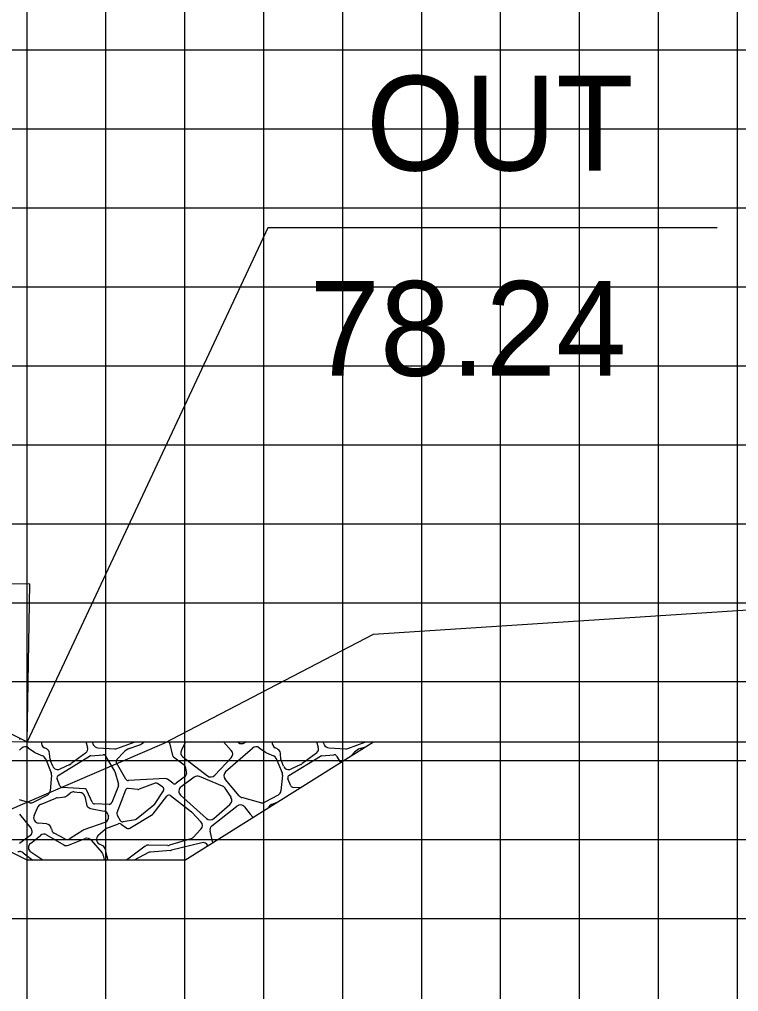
# Model space of a CAD drawing. Extents: x 857504 to 857847, y 364765 to 364985.
# Drawn here: x 857733.21 to 857742.32, y 364923.38 to 364935.69 of the extents above; entities that cross this region are included whole.
import ezdxf

# ---------------------------------------------------------------- set-up
doc = ezdxf.new("R2010")
doc.units = 0
for name, color, linetype in [('ANNOTATION', 7, 'Continuous'), ('D_Drainage_Culvert', 7, 'Continuous'), ('D_Roadway_Centerline', 7, 'Continuous'), ('D_Roadway_SlopeLines', 7, 'Continuous'), ('MAJOR', 7, 'Continuous'), ('MINOR', 7, 'Continuous'), ('S_Roadway_Centerline', 7, 'Continuous')]:
    doc.layers.add(name, color=color, linetype=linetype)

msp = doc.modelspace()

# ---------------------------------------------------------------- linework, layer by layer
at = {"layer": 'ANNOTATION'}
msp.add_lwpolyline([(857742.052, 364933.049), (857736.36, 364933.049), (857733.308, 364926.539)], dxfattribs=at)
at = {"layer": 'D_Drainage_Culvert'}
for p, q in [((857596.788, 364931.1), (857733.345, 364928.539)), ((857596.751, 364929.101), (857733.308, 364926.539)), ((857733.308, 364926.539), (857733.345, 364928.539))]:
    msp.add_line(p, q, dxfattribs=at)
at = {"layer": 'D_Roadway_Centerline'}
msp.add_lwpolyline([(857596.751, 364929.101), (857642.099, 364951.775), (857647.308, 364954.379), (857650.308, 364954.439), (857655.308, 364954.539), (857669.308, 364953.699), (857677.308, 364953.219), (857680.308, 364953.039), (857685.989, 364950.198), (857733.308, 364926.539)], dxfattribs=at)
at = {"layer": 'D_Roadway_SlopeLines'}
for p, q in [((857733.227, 364926.579), (857733.212, 364926.57)), ((857734.051, 364926.539), (857734.073, 364926.474)), ((857734.132, 364926.539), (857734.147, 364926.504)), ((857734.446, 364926.455), (857734.678, 364926.539)), ((857734.603, 364926.455), (857734.723, 364926.496)), ((857734.769, 364926.521), (857734.794, 364926.539)), ((857735.113, 364926.525), (857735.151, 364926.368)), ((857735.307, 364926.522), (857735.263, 364926.433)), ((857735.308, 364926.539), (857809.308, 364926.539)), ((857735.308, 364925.039), (857737.697, 364926.539)), ((857735.896, 364926.429), (857735.797, 364926.539)), ((857735.987, 364926.53), (857735.975, 364926.539)), ((857736.084, 364926.539), (857736.062, 364926.526)), ((857736.975, 364926.539), (857736.997, 364926.474)), ((857737.056, 364926.539), (857737.072, 364926.504)), ((857737.37, 364926.455), (857737.602, 364926.539)), ((857737.528, 364926.455), (857737.607, 364926.482)), ((857733.212, 364926.436), (857733.239, 364926.46)), ((857733.324, 364926.465), (857733.403, 364926.409)), ((857733.415, 364926.402), (857733.504, 364926.363)), ((857733.557, 364926.449), (857733.527, 364926.464)), ((857733.6, 364926.318), (857733.593, 364926.394)), ((857733.702, 364926.114), (857734.101, 364926.359)), ((857734.049, 364926.398), (857733.864, 364926.259)), ((857734.116, 364926.364), (857734.271, 364926.377)), ((857734.206, 364926.463), (857734.419, 364926.451)), ((857734.304, 364926.36), (857734.415, 364926.17)), ((857734.446, 364926.314), (857734.534, 364926.409)), ((857735.824, 364926.162), (857736.136, 364926.436)), ((857736.136, 364926.436), (857736.164, 364926.46)), ((857736.249, 364926.465), (857736.327, 364926.409)), ((857736.34, 364926.402), (857736.429, 364926.363)), ((857736.482, 364926.449), (857736.452, 364926.464)), ((857736.525, 364926.318), (857736.518, 364926.394)), ((857736.626, 364926.114), (857737.025, 364926.359)), ((857736.974, 364926.398), (857736.789, 364926.259)), ((857737.04, 364926.364), (857737.196, 364926.377)), ((857737.131, 364926.463), (857737.343, 364926.451)), ((857737.228, 364926.36), (857737.278, 364926.276)), ((857737.414, 364926.361), (857737.458, 364926.409)), ((857733.54, 364926.327), (857733.614, 364926.148)), ((857733.634, 364926.23), (857733.606, 364926.297)), ((857733.851, 364926.251), (857733.725, 364926.195)), ((857734.56, 364926.066), (857734.441, 364926.274)), ((857735.164, 364926.348), (857735.3, 364926.249)), ((857735.282, 364926.348), (857735.594, 364926.11)), ((857735.685, 364926.117), (857735.894, 364926.337)), ((857736.465, 364926.327), (857736.538, 364926.148)), ((857736.559, 364926.23), (857736.53, 364926.297)), ((857736.776, 364926.251), (857736.649, 364926.195)), ((857733.619, 364926.116), (857733.601, 364925.92)), ((857734.419, 364926.163), (857734.467, 364926.005)), ((857735.313, 364926.227), (857735.327, 364926.138)), ((857736.543, 364926.116), (857736.525, 364925.92)), ((857733.725, 364925.983), (857733.688, 364926.072)), ((857735.064, 364926.074), (857734.591, 364926.049)), ((857734.93, 364926.015), (857734.727, 364925.939)), ((857735.028, 364925.967), (857734.961, 364926.011)), ((857735.154, 364926.015), (857735.087, 364926.067)), ((857735.314, 364926.105), (857735.196, 364926.015)), ((857735.425, 364926.094), (857735.259, 364925.971)), ((857735.786, 364925.978), (857735.493, 364926.102)), ((857735.994, 364925.855), (857735.817, 364926.066)), ((857736.65, 364925.983), (857736.613, 364926.072)), ((857733.565, 364925.866), (857733.394, 364925.775)), ((857734.038, 364925.945), (857733.755, 364925.962)), ((857733.817, 364925.859), (857733.855, 364925.891)), ((857733.906, 364925.907), (857733.979, 364925.9)), ((857734.133, 364925.775), (857734.067, 364925.925)), ((857734.466, 364925.982), (857734.381, 364925.77)), ((857734.555, 364925.927), (857734.446, 364925.642)), ((857734.712, 364925.937), (857734.591, 364925.949)), ((857734.923, 364925.748), (857735.037, 364925.919)), ((857735.254, 364925.865), (857735.582, 364925.568)), ((857735.892, 364925.837), (857735.817, 364925.952)), ((857736.49, 364925.866), (857736.319, 364925.775)), ((857736.769, 364925.956), (857736.679, 364925.962)), ((857733.345, 364925.769), (857733.212, 364925.804)), ((857733.479, 364925.747), (857733.672, 364925.827)), ((857733.69, 364925.832), (857733.781, 364925.843)), ((857734.039, 364925.846), (857734.06, 364925.749)), ((857734.348, 364925.748), (857734.163, 364925.754)), ((857734.696, 364925.564), (857734.916, 364925.74)), ((857734.905, 364925.628), (857735.077, 364925.853)), ((857735.125, 364925.859), (857735.391, 364925.655)), ((857735.673, 364925.567), (857735.879, 364925.748)), ((857736.136, 364925.804), (857736.029, 364925.833)), ((857736.269, 364925.769), (857736.136, 364925.804)), ((857736.404, 364925.747), (857736.496, 364925.785)), ((857733.212, 364925.625), (857733.358, 364925.447)), ((857733.397, 364925.606), (857733.443, 364925.711)), ((857734.113, 364925.697), (857734.284, 364925.662)), ((857734.61, 364925.446), (857734.896, 364925.619)), ((857735.395, 364925.651), (857735.511, 364925.526)), ((857735.65, 364925.477), (857735.966, 364925.726)), ((857736.061, 364925.716), (857736.136, 364925.625)), ((857736.136, 364925.625), (857736.172, 364925.582)), ((857736.363, 364925.702), (857736.367, 364925.711)), ((857733.555, 364925.5), (857733.452, 364925.511)), ((857734.295, 364925.519), (857734.028, 364925.425)), ((857734.306, 364925.44), (857734.468, 364925.503)), ((857734.337, 364925.61), (857734.339, 364925.599)), ((857734.448, 364925.612), (857734.488, 364925.545)), ((857734.5, 364925.499), (857734.573, 364925.447)), ((857734.524, 364925.529), (857734.681, 364925.557)), ((857733.616, 364925.435), (857733.615, 364925.44)), ((857733.785, 364925.313), (857733.652, 364925.383)), ((857734.014, 364925.418), (857733.854, 364925.316)), ((857734.21, 364925.356), (857734.296, 364925.433)), ((857735.51, 364925.433), (857735.412, 364925.33)), ((857735.661, 364925.261), (857735.626, 364925.407)), ((857733.345, 364925.349), (857733.212, 364925.251)), ((857733.351, 364925.253), (857733.478, 364925.355)), ((857733.555, 364925.361), (857733.773, 364925.235)), ((857733.832, 364925.231), (857734.043, 364925.314)), ((857734.12, 364925.295), (857734.258, 364925.134)), ((857735.383, 364925.311), (857735.112, 364925.229)), ((857735.521, 364925.262), (857735.137, 364925.167)), ((857733.257, 364925.135), (857733.381, 364925.039)), ((857733.507, 364925.039), (857733.355, 364925.144)), ((857734.268, 364925.222), (857734.225, 364925.245)), ((857734.322, 364925.083), (857734.303, 364925.175)), ((857734.806, 364925.219), (857734.567, 364925.039)), ((857734.847, 364925.136), (857734.663, 364925.039)), ((857735.09, 364925.226), (857734.849, 364925.233)), ((857735.126, 364925.165), (857734.873, 364925.144)), ((857734.273, 364925.102), (857734.283, 364925.048)), ((857734.337, 364925.039), (857734.324, 364925.074))]:
    msp.add_line(p, q, dxfattribs=at)
for points in [[(857680.308, 364953.039), (857733.308, 364926.539)], [(857735.308, 364925.039), (857733.308, 364925.039), (857727.362, 364928.012)], [(857733.308, 364926.539), (857735.308, 364926.539)]]:
    msp.add_lwpolyline(points, dxfattribs=at)
for centre, radius, start, end in [((857733.285, 364926.409), 0.0684, 54.7824, 131.257), ((857733.559, 364926.525), 0.0684, 167.9869, 242.3005), ((857734.21, 364926.531), 0.0684, 203.7495, 266.7755), ((857734.667, 364926.658), 0.171, 289.1336, 306.7644), ((857735.08, 364926.516), 0.0342, 13.7608, 41.531), ((857735.368, 364926.491), 0.0684, 135.5801, 153.4931), ((857736.028, 364926.585), 0.0684, 233.4711, 300.6507), ((857736.209, 364926.409), 0.0684, 54.7824, 131.257), ((857736.483, 364926.525), 0.0684, 167.9869, 242.3005), ((857737.135, 364926.531), 0.0684, 203.7495, 266.7755), ((857733.442, 364926.465), 0.0684, 234.7824, 246.3706), ((857733.477, 364926.3), 0.0684, 22.4794, 66.3706), ((857733.525, 364926.388), 0.0684, 5.1944, 62.3005), ((857734.008, 364926.452), 0.0684, 307.0199, 18.7413), ((857734.118, 364926.33), 0.0342, 94.6669, 121.5514), ((857734.274, 364926.343), 0.0342, 30.5102, 94.6669), ((857734.422, 364926.519), 0.0684, 266.7755, 289.9256), ((857734.659, 364926.293), 0.171, 109.1336, 137.3215), ((857735.184, 364926.376), 0.0342, 193.7608, 233.6864), ((857735.324, 364926.402), 0.0684, 153.4931, 232.6367), ((857735.845, 364926.384), 0.0684, 316.4321, 41.8334), ((857736.367, 364926.465), 0.0684, 234.7824, 246.3706), ((857736.401, 364926.3), 0.0684, 22.4794, 66.3706), ((857736.45, 364926.388), 0.0684, 5.1944, 62.3005), ((857736.933, 364926.452), 0.0684, 307.0199, 18.7413), ((857737.043, 364926.33), 0.0342, 94.6669, 121.5514), ((857737.199, 364926.343), 0.0342, 30.5102, 94.6669), ((857737.347, 364926.519), 0.0684, 266.7755, 289.9256), ((857737.584, 364926.293), 0.171, 109.1336, 137.3215), ((857733.668, 364926.324), 0.0684, 185.1944, 203.3852), ((857733.823, 364926.313), 0.0684, 293.8602, 307.0199), ((857734.471, 364926.291), 0.0342, 137.3215, 209.792), ((857735.279, 364926.221), 0.0342, 8.7462, 53.6864), ((857736.593, 364926.324), 0.0684, 185.1944, 203.3852), ((857736.748, 364926.313), 0.0684, 293.8602, 307.0199), ((857733.55, 364926.122), 0.0684, 354.8056, 22.4794), ((857733.697, 364926.257), 0.0684, 203.3852, 293.8602), ((857733.72, 364926.085), 0.0342, 121.5514, 202.6199), ((857734.386, 364926.153), 0.0342, 16.9275, 30.5102), ((857735.293, 364926.133), 0.0342, 307.5348, 8.7462), ((857735.466, 364926.039), 0.0684, 66.9778, 126.6071), ((857735.636, 364926.164), 0.0684, 232.6367, 316.4321), ((857735.869, 364926.11), 0.0684, 131.257, 219.9575), ((857736.475, 364926.122), 0.0684, 354.8056, 22.4794), ((857736.622, 364926.257), 0.0684, 203.3852, 293.8602), ((857736.644, 364926.085), 0.0342, 121.5514, 202.6199), ((857734.434, 364925.995), 0.0342, 338.1986, 16.9275), ((857734.59, 364926.083), 0.0342, 209.792, 272.9903), ((857734.942, 364925.983), 0.0342, 56.3099, 110.4835), ((857735.066, 364926.039), 0.0342, 52.4314, 92.9903), ((857735.175, 364926.042), 0.0342, 232.4314, 307.5348), ((857733.533, 364925.926), 0.0684, 298.0725, 354.8056), ((857733.757, 364925.996), 0.0342, 202.6199, 266.6726), ((857733.899, 364925.839), 0.0684, 84.2894, 130.3645), ((857733.972, 364925.832), 0.0684, 12.4074, 84.2894), ((857734.036, 364925.911), 0.0342, 23.7495, 86.6726), ((857734.587, 364925.915), 0.0342, 84.4278, 159.0071), ((857734.715, 364925.971), 0.0342, 264.4278, 290.4835), ((857735.009, 364925.938), 0.0342, 326.3099, 56.3099), ((857735.104, 364925.832), 0.0342, 52.5946, 142.5946), ((857735.3, 364925.916), 0.0684, 126.6071, 227.8776), ((857735.76, 364925.915), 0.0684, 32.9625, 66.9778), ((857736.457, 364925.926), 0.0684, 298.0725, 354.8056), ((857736.681, 364925.996), 0.0342, 202.6199, 266.6726), ((857733.362, 364925.835), 0.0684, 255.2564, 298.0725), ((857733.505, 364925.683), 0.0684, 112.6199, 156.3179), ((857733.698, 364925.764), 0.0684, 97.125, 112.6199), ((857733.773, 364925.911), 0.0684, 277.125, 310.3645), ((857734.127, 364925.764), 0.0684, 192.4074, 258.3664), ((857734.164, 364925.788), 0.0342, 203.7495, 268.1221), ((857734.349, 364925.782), 0.0342, 268.1221, 338.1986), ((857734.894, 364925.767), 0.0342, 308.7742, 326.3099), ((857735.834, 364925.799), 0.0684, 311.2462, 32.9625), ((857736.008, 364925.673), 0.0684, 39.4712, 128.373), ((857736.047, 364925.899), 0.0684, 219.9575, 255.2564), ((857736.287, 364925.835), 0.0684, 255.2564, 298.0725), ((857736.43, 364925.683), 0.0684, 112.6199, 156.3179), ((857734.27, 364925.595), 0.0684, 13.134, 78.3664), ((857734.478, 364925.63), 0.0342, 159.0071, 210.6507), ((857734.878, 364925.649), 0.0342, 301.373, 322.5946), ((857735.37, 364925.628), 0.0342, 42.7891, 52.5946), ((857733.46, 364925.579), 0.0684, 156.3179, 263.9458), ((857733.547, 364925.432), 0.0684, 6.8428, 83.9458), ((857734.273, 364925.584), 0.0684, 289.406, 13.134), ((857734.481, 364925.471), 0.0342, 54.4623, 111.1941), ((857734.518, 364925.562), 0.0342, 210.6507, 280.204), ((857734.675, 364925.591), 0.0342, 280.204, 308.7742), ((857735.461, 364925.48), 0.0684, 316.3639, 42.7891), ((857735.628, 364925.619), 0.0684, 227.8776, 311.2462), ((857733.305, 364925.404), 0.0684, 306.2192, 39.4712), ((857733.521, 364925.302), 0.0684, 59.9314, 128.8845), ((857733.684, 364925.444), 0.0684, 186.8428, 242.1524), ((857734.051, 364925.361), 0.0684, 109.406, 122.6806), ((857734.319, 364925.408), 0.0342, 111.1941, 132.2073), ((857734.593, 364925.475), 0.0342, 234.4623, 301.373), ((857735.693, 364925.423), 0.0684, 128.373, 193.5819), ((857733.394, 364925.2), 0.0684, 128.8845, 235.4375), ((857733.817, 364925.373), 0.0684, 242.1524, 302.6806), ((857734.068, 364925.25), 0.0684, 40.6013, 111.541), ((857734.256, 364925.305), 0.0684, 132.2073, 242.354), ((857735.363, 364925.377), 0.0684, 286.8986, 316.3639), ((857735.537, 364925.195), 0.0684, 23.6332, 103.8595), ((857733.215, 364925.081), 0.0684, 92.6788, 109.44), ((857733.215, 364925.081), 0.0684, 52.3058, 92.6788), ((857733.807, 364925.294), 0.0684, 239.9314, 291.541), ((857734.206, 364925.09), 0.0684, 10.3048, 40.6013), ((857734.236, 364925.162), 0.0684, 11.6336, 62.354), ((857734.848, 364925.164), 0.0684, 88.4306, 126.9888), ((857734.879, 364925.076), 0.0684, 94.7636, 117.8015), ((857735.092, 364925.295), 0.0684, 268.4306, 286.8986), ((857735.12, 364925.233), 0.0684, 274.7636, 283.8595), ((857734.216, 364925.036), 0.0684, 2.9654, 10.3048), ((857734.389, 364925.097), 0.0684, 191.6336, 199.5367)]:
    msp.add_arc(centre, radius, start, end, dxfattribs=at)
at = {"layer": 'MAJOR'}
for p, q in [((857739.308, 364918.302), (857739.308, 364963.302)), ((857529.308, 364933.302), (857809.308, 364933.302)), ((857529.308, 364928.302), (857809.308, 364928.302))]:
    msp.add_line(p, q, dxfattribs=at)
at = {"layer": 'MINOR'}
for p, q in [((857733.308, 364918.302), (857733.308, 364963.302)), ((857734.308, 364918.302), (857734.308, 364963.302)), ((857735.308, 364918.302), (857735.308, 364963.302)), ((857736.308, 364918.302), (857736.308, 364963.302)), ((857737.308, 364918.302), (857737.308, 364963.302)), ((857738.308, 364918.302), (857738.308, 364963.302)), ((857740.308, 364918.302), (857740.308, 364963.302)), ((857741.308, 364918.302), (857741.308, 364963.302)), ((857742.308, 364918.302), (857742.308, 364963.302)), ((857529.308, 364935.302), (857809.308, 364935.302)), ((857529.308, 364934.302), (857809.308, 364934.302)), ((857529.308, 364932.302), (857809.308, 364932.302)), ((857529.308, 364931.302), (857809.308, 364931.302)), ((857529.308, 364930.302), (857809.308, 364930.302)), ((857529.308, 364929.302), (857809.308, 364929.302)), ((857529.308, 364927.302), (857809.308, 364927.302)), ((857529.308, 364926.302), (857809.308, 364926.302)), ((857529.308, 364925.302), (857809.308, 364925.302)), ((857529.308, 364924.302), (857809.308, 364924.302))]:
    msp.add_line(p, q, dxfattribs=at)
at = {"layer": 'S_Roadway_Centerline'}
msp.add_lwpolyline([(857714.491, 364924.707), (857723.7, 364923.452), (857723.875, 364923.476), (857724.627, 364923.626), (857729.419, 364924.342), (857730.665, 364924.767), (857732.057, 364925.31), (857732.425, 364925.446), (857732.667, 364925.491), (857732.758, 364925.539), (857735.045, 364926.522), (857737.697, 364927.904), (857750.562, 364928.741), (857755.69, 364929.224), (857762.41, 364929.29), (857785.258, 364929.461), (857785.627, 364929.463), (857785.734, 364929.462), (857785.931, 364929.461), (857801.042, 364929.474), (857809.308, 364929.511)], dxfattribs=at)

# ---------------------------------------------------------------- texts
at = {"layer": 'ANNOTATION'}
for s, p in [('OUT', (857737.603, 364933.775)), ('78.24', (857736.886, 364931.175))]:
    msp.add_text(s, height=1.2, dxfattribs=at).set_placement(p)

doc.saveas('drawing.dxf')
